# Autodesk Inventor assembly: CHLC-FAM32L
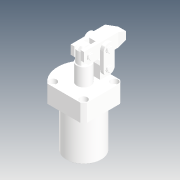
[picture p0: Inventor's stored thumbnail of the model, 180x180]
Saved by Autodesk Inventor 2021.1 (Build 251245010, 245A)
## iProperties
Created: 2019-04
Part Number: CHLC-FAM32L
Description: STEP AP214
Document SubType Name: Assembly
Designer: user
Title: CHLC-FAM32L.STEP
Revision Number: ÈÎºÎ
Sending System: SolidWorks 2016
Preprocessor: SwSTEP 2.0
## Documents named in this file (10)
- D:\Vault_2016\Projekty\Clamptek\Hydraulic\CHLC\CHLC-32\Inventor\CHLC-FAM32L\CHLC-FAM32L.iam
- D:\Vault_2016\Projekty\Clamptek\Hydraulic\CHLC\CHLC-32\Inventor\CHLC-FAM32L\CHLC-FAM32-05_1.ipt
- D:\Vault_2016\Projekty\Clamptek\Hydraulic\CHLC\CHLC-32\Inventor\CHLC-FAM32L\CHLC-32-02_1.ipt
- D:\Vault_2016\Projekty\Clamptek\Hydraulic\CHLC\CHLC-32\Inventor\CHLC-FAM32L\CHLC-32-03_1.ipt
- D:\Vault_2016\Projekty\Clamptek\Hydraulic\CHLC\CHLC-32\Inventor\CHLC-FAM32L\CHLC-32-04_1_1.ipt
- D:\Vault_2016\Projekty\Clamptek\Hydraulic\CHLC\CHLC-32\Inventor\CHLC-FAM32L\CHLC-32-08_1.ipt
- D:\Vault_2016\Projekty\Clamptek\Hydraulic\CHLC\CHLC-32\Inventor\CHLC-FAM32L\LHC01D-32-01_1.ipt
- D:\Vault_2016\Projekty\Clamptek\Hydraulic\CHLC\CHLC-32\Inventor\CHLC-FAM32L\YAKUAI.ipt
- D:\Vault_2016\Projekty\Clamptek\Hydraulic\CHLC\CHLC-32\Inventor\CHLC-FAM32L\socket set screw flat point_iso_ISO 4026 - M5 x 6-N.ipt
- D:\Vault_2016\Projekty\Clamptek\Hydraulic\CHLC\CHLC-32\Inventor\CHLC-FAM32L\Ñ¹±Û.ipt
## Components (17 placed, 17 different names)
1. CHLC-FAM32-05_1_1
2. CHLC-32-02_1_2
3. CHLC-32-03_1_3
4. CHLC-32-03_1_4
5. CHLC-32-04_1_1_5
6. CHLC-32-08_1_6
7. LHC01D-32-01_1_7
8. YAKUAI_8
9. CHLC-32-04_1_1_9
10. LHC01D-32-01_1_10
11. LHC01D-32-01_1_11
12. LHC01D-32-01_1_12
13. LHC01D-32-01_1_13
14. LHC01D-32-01_1_14
15. socket set screw flat point_iso_ISO 4026 - M5 x 6-N_15
16. socket set screw flat point_iso_ISO 4026 - M5 x 6-N_16
17. Ñ¹±Û_17
